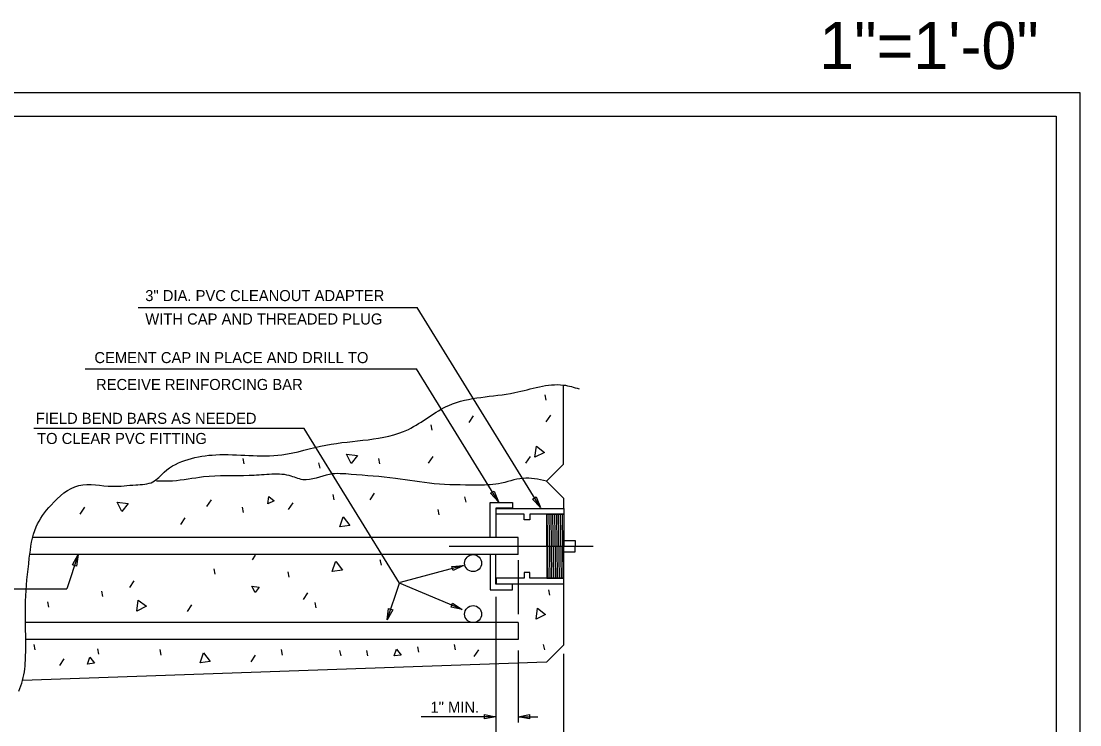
# Model space of a CAD drawing. Extents: x 0 to 2.83, y 0 to 1.96.
# Drawn here: x 0.961 to 2.833, y 0.716 to 1.96 of the extents above; entities that cross this region are included whole.
import ezdxf

# ---------------------------------------------------------------- set-up
doc = ezdxf.new("R2010")
doc.units = 0
for name, color, linetype in [('BORDER_ANNO_Cutsheet', 7, 'Continuous'), ('BRDG_ANNO_Anno-Sheet', 7, 'Continuous'), ('BRDG_ANNO_General-Notes', 7, 'Continuous'), ('BRDG_BASE_Dtlctrln', 7, 'Continuous'), ('BRDG_BASE_Obj-Line', 7, 'Continuous'), ('BRDG_BASE_Pattern', 7, 'Continuous'), ('BRDG_BASE_Rebar', 7, 'Continuous')]:
    doc.layers.add(name, color=color, linetype=linetype)

msp = doc.modelspace()

# ---------------------------------------------------------------- linework, layer by layer
at = {"layer": 'BORDER_ANNO_Cutsheet'}
msp.add_lwpolyline([(0, 1.8333), (2.8333, 1.8333), (2.8333, 0), (0, 0)], close=True, dxfattribs=at)
at = {"layer": 'BRDG_ANNO_Anno-Sheet'}
msp.add_lwpolyline([(0.125, 1.7917), (2.7917, 1.7917), (2.7917, 0.0417), (0.125, 0.0417)], close=True, dxfattribs=at)
at = {"layer": 'BRDG_ANNO_General-Notes'}
for p, q in [((1.1679, 1.4539), (1.6611, 1.4539)), ((1.8792, 1.0999), (1.6611, 1.4539)), ((1.0741, 1.3452), (1.6601, 1.3452)), ((1.8048, 1.1103), (1.6601, 1.3452)), ((1.4614, 1.24), (0.983, 1.24)), ((1.6298, 0.9666), (1.4614, 1.24)), ((1.7911, 1.1254), (1.7975, 1.1293)), ((1.8048, 1.1103), (1.7911, 1.1254)), ((1.7975, 1.1293), (1.8048, 1.1103)), ((1.8654, 1.115), (1.8719, 1.119)), ((1.8792, 1.0999), (1.8654, 1.115)), ((1.8719, 1.119), (1.8792, 1.0999)), ((1.0616, 1.0169), (1.0417, 0.9565)), ((1.0518, 0.9991), (1.0616, 1.0169)), ((1.0616, 1.0169), (1.0589, 0.9967)), ((1.0589, 0.9967), (1.0518, 0.9991)), ((1.7431, 0.9974), (1.6314, 0.9677)), ((1.7228, 0.9959), (1.7431, 0.9974)), ((1.7247, 0.9886), (1.7228, 0.9959)), ((1.7431, 0.9974), (1.7247, 0.9886)), ((1.8401, 1.0069), (1.8401, 0.9116)), ((0.5272, 0.9565), (1.0417, 0.9565)), ((1.6079, 0.9018), (1.6302, 0.9666)), ((1.741, 0.92), (1.6302, 0.9666)), ((1.8001, 0.9426), (1.8001, 0.6503)), ((1.6079, 0.9018), (1.6108, 0.9219)), ((1.6179, 0.9194), (1.6079, 0.9018)), ((1.6108, 0.9219), (1.6179, 0.9194)), ((1.7211, 0.9243), (1.724, 0.9311)), ((1.741, 0.92), (1.7211, 0.9243)), ((1.724, 0.9311), (1.741, 0.92)), ((1.8401, 0.8476), (1.8401, 0.7203)), ((1.9201, 0.8415), (1.9201, 0.6503)), ((1.8001, 0.7303), (1.6681, 0.7303)), ((1.7801, 0.7266), (1.7801, 0.7341)), ((1.7801, 0.7341), (1.8001, 0.7303)), ((1.8001, 0.7303), (1.7801, 0.7266)), ((1.8401, 0.7303), (1.8601, 0.7341)), ((1.8401, 0.7303), (1.8749, 0.7303)), ((1.8601, 0.7266), (1.8401, 0.7303)), ((1.8601, 0.7341), (1.8601, 0.7266))]:
    msp.add_line(p, q, dxfattribs=at)
at = {"layer": 'BRDG_BASE_Dtlctrln'}
msp.add_line((1.718, 1.0319), (1.9723, 1.0319), dxfattribs=at)
at = {"layer": 'BRDG_BASE_Obj-Line'}
for p, q in [((1.9201, 1.1769), (1.9201, 1.3166)), ((1.8901, 1.1469), (1.9201, 1.1769)), ((1.8901, 1.1469), (1.9201, 1.1169)), ((1.7901, 1.0469), (1.7901, 1.109)), ((1.7901, 1.109), (1.8301, 1.109)), ((1.8301, 1.109), (1.8301, 1.099)), ((1.9201, 1.1169), (1.9201, 1.0985)), ((1.8301, 1.099), (1.8001, 1.099)), ((1.8001, 1.099), (1.8001, 1.0469)), ((1.8001, 1.0869), (1.8001, 1.0569)), ((1.8007, 1.0985), (1.9207, 1.0985)), ((1.8007, 1.0885), (1.8007, 1.0985)), ((1.8507, 1.0885), (1.8007, 1.0885)), ((1.8507, 1.0785), (1.8507, 1.0885)), ((1.9207, 1.0885), (1.8607, 1.0885)), ((1.8607, 1.0885), (1.8607, 1.0785)), ((1.8907, 1.0319), (1.8907, 1.0885)), ((1.8907, 1.0885), (1.9207, 1.0885)), ((1.8907, 1.0885), (1.8924, 0.9752)), ((1.8924, 0.9752), (1.8907, 1.0885)), ((1.8907, 1.0885), (1.8924, 0.9752)), ((1.8907, 1.0885), (1.8924, 0.9752)), ((1.8941, 1.0885), (1.8957, 0.9752)), ((1.8974, 1.0885), (1.8991, 0.9752)), ((1.9007, 1.0885), (1.9024, 0.9752)), ((1.9041, 1.0885), (1.9057, 0.9752)), ((1.9074, 1.0885), (1.9091, 0.9752)), ((1.9107, 1.0885), (1.9124, 0.9752)), ((1.9141, 1.0885), (1.9157, 0.9752)), ((1.9174, 1.0885), (1.9191, 0.9752)), ((1.9207, 1.0985), (1.9207, 1.0885)), ((1.9207, 1.0885), (1.9207, 1.0419)), ((1.8607, 1.0785), (1.8507, 1.0785)), ((1.8907, 1.0319), (1.8907, 0.9752)), ((1.9207, 1.0419), (1.9407, 1.0419)), ((1.9207, 1.0419), (1.9207, 1.0319)), ((1.9207, 1.0219), (1.9207, 1.0319)), ((1.9407, 1.0419), (1.9407, 1.0319)), ((1.9407, 1.0219), (1.9407, 1.0319)), ((1.7901, 1.0169), (1.7901, 0.9548)), ((1.8001, 0.9648), (1.8001, 1.0169)), ((1.9207, 0.9752), (1.9207, 1.0219)), ((1.9207, 1.0219), (1.9407, 1.0219)), ((1.8507, 0.9753), (1.8007, 0.9753)), ((1.8007, 0.9753), (1.8007, 0.9653)), ((1.8607, 0.9853), (1.8507, 0.9853)), ((1.8507, 0.9853), (1.8507, 0.9753)), ((1.8607, 0.9753), (1.8607, 0.9853)), ((1.9207, 0.9753), (1.8607, 0.9753)), ((1.8907, 0.9752), (1.9207, 0.9752)), ((1.9207, 0.9653), (1.9207, 0.9753)), ((1.8301, 0.9648), (1.8001, 0.9648)), ((1.8007, 0.9653), (1.9207, 0.9653)), ((1.8301, 0.9548), (1.8301, 0.9648)), ((1.9201, 0.9645), (1.9201, 0.8569)), ((1.7901, 0.9548), (1.8301, 0.9548)), ((1.9201, 0.8569), (1.8901, 0.8269)), ((1.8901, 0.8269), (0.9632, 0.7946))]:
    msp.add_line(p, q, dxfattribs=at)
for points in [[(0.9567, 0.7759), (0.9632, 0.7946), (0.9686, 0.8355), (0.9686, 0.9349), (0.9752, 1.0104), (0.9872, 1.066), (1.0136, 1.1045), (1.0627, 1.139), (1.1223, 1.1376), (1.1633, 1.1403), (1.1939, 1.1456), (1.2137, 1.1628), (1.2561, 1.1853), (1.3051, 1.1933), (1.4218, 1.1933), (1.4999, 1.2105), (1.6456, 1.2383), (1.7172, 1.2807), (1.8339, 1.3032), (1.9201, 1.3166), (1.9478, 1.3099)], [(1.8901, 1.1469), (1.848, 1.1517), (1.8053, 1.1422), (1.765, 1.1398), (1.6914, 1.1422), (1.6226, 1.1517), (1.5443, 1.1587), (1.5062, 1.1587), (1.4589, 1.1493), (1.4351, 1.1565), (1.3995, 1.1587), (1.3639, 1.1565), (1.2832, 1.1541), (1.2286, 1.1469), (1.2001, 1.1469)]]:
    msp.add_spline(points, degree=3, dxfattribs=at)
at = {"layer": 'BRDG_BASE_Pattern'}
for p, q in [((1.8895, 1.29), (1.8876, 1.2994)), ((1.753, 1.2503), (1.7609, 1.2622)), ((1.8895, 1.2516), (1.8974, 1.2635)), ((1.688, 1.237), (1.6861, 1.2465)), ((1.3555, 1.1774), (1.3536, 1.1868)), ((1.5953, 1.1774), (1.5934, 1.1868)), ((1.6815, 1.1787), (1.6894, 1.1906)), ((1.8536, 1.1787), (1.8617, 1.1906)), ((1.4894, 1.1694), (1.4874, 1.1789)), ((1.5781, 1.1138), (1.586, 1.1257)), ((1.2893, 1.1019), (1.2972, 1.1138)), ((1.4336, 1.0966), (1.4417, 1.1085)), ((1.5145, 1.1138), (1.5126, 1.1232)), ((1.7477, 1.1098), (1.7458, 1.1192)), ((1.0653, 1.0886), (1.0733, 1.1005)), ((1.3542, 1.0913), (1.3523, 1.1007)), ((1.7, 1.0873), (1.6981, 1.0967)), ((1.2429, 1.0701), (1.2508, 1.082)), ((1.3701, 1.0078), (1.3754, 1.0158)), ((1.5965, 1.0061), (1.596, 1.0079)), ((1.598, 0.9985), (1.5965, 1.0061)), ((1.3039, 0.9826), (1.302, 0.992)), ((1.435, 0.9773), (1.4331, 0.9867)), ((1.1528, 0.9587), (1.1607, 0.9707)), ((1.1051, 0.9428), (1.1032, 0.9523)), ((1.4602, 0.9376), (1.4681, 0.9495)), ((1.896, 0.9455), (1.8942, 0.9549)), ((1.0097, 0.9243), (1.0078, 0.9337)), ((1.2548, 0.9164), (1.2627, 0.9283)), ((1.4827, 0.923), (1.4808, 0.9324)), ((0.9858, 0.8488), (0.984, 0.8582)), ((1.0984, 0.8408), (1.0966, 0.8502)), ((1.2084, 0.8395), (1.2066, 0.849)), ((1.4231, 0.8395), (1.4211, 0.849)), ((1.5265, 0.8382), (1.5246, 0.8476)), ((1.5742, 0.8382), (1.5723, 0.8476)), ((1.6643, 0.8448), (1.6623, 0.8542)), ((1.7292, 0.8488), (1.7273, 0.8582)), ((1.7623, 0.8369), (1.7702, 0.8488)), ((1.8868, 0.8488), (1.8849, 0.8582)), ((1.0289, 0.8207), (1.0368, 0.8327)), ((1.3674, 0.8276), (1.3754, 0.8395))]:
    msp.add_line(p, q, dxfattribs=at)
for points in [[(1.8694, 1.1892), (1.872, 1.2086), (1.8864, 1.1976)], [(1.536, 1.1947), (1.5555, 1.1922), (1.5445, 1.1778)], [(1.1306, 1.1099), (1.1501, 1.1074), (1.1391, 1.093)], [(1.3969, 1.1064), (1.3986, 1.1194), (1.4082, 1.112)], [(1.5304, 1.0839), (1.5423, 1.0683), (1.5244, 1.0659)], [(1.3686, 0.9611), (1.3818, 0.9595), (1.3744, 0.9498)], [(1.1654, 0.9171), (1.1679, 0.9366), (1.1823, 0.9256)], [(1.8717, 0.9026), (1.8742, 0.922), (1.8885, 0.911)], [(1.283, 0.8436), (1.295, 0.828), (1.2771, 0.8257)], [(1.6247, 0.8499), (1.6327, 0.8395), (1.6207, 0.8379)], [(1.0823, 0.8356), (1.0903, 0.8252), (1.0782, 0.8236)]]:
    msp.add_lwpolyline(points, close=True, dxfattribs=at)
for points in [[(1.5178, 1.004), (1.5291, 0.9893), (1.5111, 0.9869), (1.5169, 1.004)], [(1.5169, 1.004), (1.5171, 1.0048)], [(1.5171, 1.0048), (1.5178, 1.004)]]:
    msp.add_lwpolyline(points, dxfattribs=at)
at = {"layer": 'BRDG_BASE_Rebar'}
for p, q in [((1.8401, 1.0469), (0.9816, 1.0469)), ((1.8401, 1.0169), (1.8401, 1.0469)), ((1.8401, 1.0169), (0.976, 1.0169)), ((1.8401, 0.8969), (0.9683, 0.8969)), ((1.8401, 0.8969), (1.8401, 0.8669)), ((1.8401, 0.8669), (0.9689, 0.8669))]:
    msp.add_line(p, q, dxfattribs=at)
for centre in [(1.7601, 1.0019), (1.7601, 0.9119)]:
    msp.add_circle(centre, 0.015, dxfattribs=at)

# ---------------------------------------------------------------- texts
at = {"layer": 'BRDG_ANNO_Anno-Sheet'}
msp.add_text('1"=1\'-0"', height=0.08333, dxfattribs=at).set_placement((2.3722, 1.875))
at = {"layer": 'BRDG_ANNO_General-Notes'}
for s, height, p in [('3" DIA. PVC CLEANOUT ADAPTER', 0.019531, (1.1802, 1.4649)), ('WITH CAP AND THREADED PLUG', 0.019531, (1.1803, 1.4235)), ('CEMENT CAP IN PLACE AND DRILL TO', 0.019531, (1.0903, 1.3553)), ('RECEIVE REINFORCING BAR', 0.019531, (1.0931, 1.3078)), ('FIELD BEND BARS AS NEEDED', 0.019531, (0.9867, 1.248)), ('TO CLEAR PVC FITTING', 0.019531, (0.9889, 1.2124)), ('1" MIN.', 0.01953, (1.6847, 0.7375))]:
    msp.add_text(s, height=height, dxfattribs=at).set_placement(p)

doc.saveas('drawing.dxf')
